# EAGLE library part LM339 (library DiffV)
Low Power Low Offset Voltage Quad Comparators with open collector; LM139/LM239/LM339/LM2901/LM3302
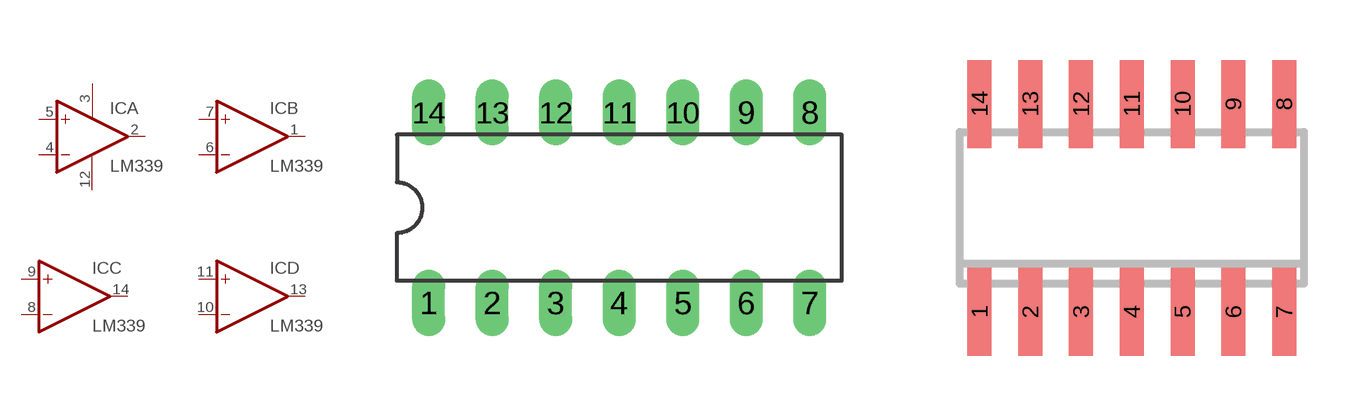
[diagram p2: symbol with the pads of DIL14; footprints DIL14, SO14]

Designator prefix IC; gates P=PWR+G A=COMPARATOR-OC B=COMPARATOR-OC C=COMPARATOR-OC D=COMPARATOR-OC

## LM339N  [DIL14]
1  B:OUT  oc
2  A:OUT  oc
3  P:V+  pwr
4  A:-IN  in
5  A:+IN  in
6  B:-IN  in
7  B:+IN  in
8  C:-IN  in
9  C:+IN  in
10  D:-IN  in
11  D:+IN  in
12  P:GND  pwr
13  D:OUT  oc
14  C:OUT  oc

## LM339D  [SO14]
Pads as for DIL14

## LM339PW  [S14]
Pads as for DIL14

## Footprint DIL14 (pad centres in mm)
Dual In Line Package
drill 0.813 long: 1 -7.62,-3.81; 2 -5.08,-3.81; 3 -2.54,-3.81; 4 0,-3.81; 5 2.54,-3.81; 6 5.08,-3.81; 7 7.62,-3.81; 8 7.62,3.81; 9 5.08,3.81; 10 2.54,3.81; 11 0,3.81; 12 -2.54,3.81; 13 -5.08,3.81; 14 -7.62,3.81

## Footprint SO14 (pad centres in mm)
Small Outline Package 14
smd 0.6 x 2.2: 1 -3.81,-2.6; 2 -2.54,-2.6; 3 -1.27,-2.6; 4 0,-2.6; 5 1.27,-2.6; 6 2.54,-2.6; 7 3.81,-2.6; 8 3.81,2.6; 9 2.54,2.6; 10 1.27,2.6; 11 0,2.6; 12 -1.27,2.6; 13 -2.54,2.6; 14 -3.81,2.6

## Footprint S14 (pad centres in mm)
SMD-Bauform "PW" 0,65 mm Beinabstand "S" steht für "Six"
smd 0.4 x 1.2: 1 -1.95,-3.25; 2 -1.3,-3.25; 3 -0.65,-3.25; 4 0,-3.25; 5 0.65,-3.25; 6 1.3,-3.25; 7 1.95,-3.25; 8 1.95,3.25; 9 1.3,3.25; 10 0.65,3.25; 11 0,3.25; 12 -0.65,3.25; 13 -1.3,3.25; 14 -1.95,3.25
